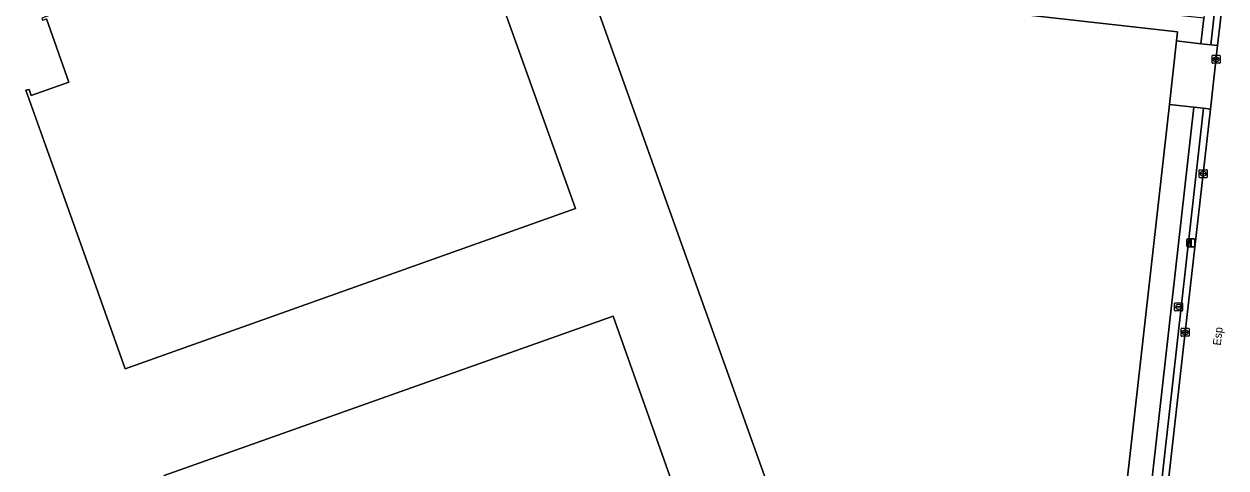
# Model space of a CAD drawing. Extents: x 161385 to 162589, y 388479 to 389756.
# Drawn here: x 162179.9 to 162330.1, y 388598.7 to 388654.2 of the extents above; entities that cross this region are included whole.
import ezdxf

# ---------------------------------------------------------------- set-up
doc = ezdxf.new("R2010")
doc.units = 0
for name, color, linetype in [('IMGEO_Berm_groen', 7, 'Continuous'), ('IMGEO_Brandkraan', 7, 'Continuous'), ('IMGEO_Erf', 7, 'Continuous'), ('IMGEO_Groenvoorziening', 7, 'Continuous'), ('IMGEO_Kolk', 7, 'Continuous'), ('IMGEO_Lichtmast', 7, 'Continuous'), ('IMGEO_Openbare_ruimte_label', 7, 'Continuous'), ('IMGEO_Pand', 7, 'Continuous'), ('IMGEO_Rijbaan_lokaal_gesloten', 7, 'Continuous'), ('IMGEO_Voetpad_open', 7, 'Continuous')]:
    doc.layers.add(name, color=color, linetype=linetype)

msp = doc.modelspace()

# ---------------------------------------------------------------- linework, layer by layer
at = {"layer": 'IMGEO_Berm_groen'}
msp.add_lwpolyline([(162322.88, 388597.19), (162324.97, 388615.65), (162327.23, 388635.47), (162328.13, 388643.54), (162327.27, 388643.64), (162321.79, 388594.96)], dxfattribs=at)
at = {"layer": 'IMGEO_Brandkraan'}
for p, q in [((162323.65, 388618.4), (162323.65, 388619.26)), ((162323.72, 388619.33), (162324.58, 388619.33)), ((162324.58, 388618.33), (162323.72, 388618.33)), ((162323.91, 388618.82), (162323.91, 388618.84)), ((162323.95, 388618.87), (162324.35, 388618.87)), ((162324.35, 388618.79), (162323.95, 388618.79)), ((162324.14, 388619.11), (162324.16, 388619.11)), ((162324.16, 388618.55), (162324.14, 388618.55)), ((162324.39, 388618.84), (162324.39, 388618.82)), ((162324.65, 388619.26), (162324.65, 388618.4))]:
    msp.add_line(p, q, dxfattribs=at)
for points in [[(162323.65, 388618.4), (162323.65, 388619.26)], [(162323.72, 388619.33), (162324.58, 388619.33)], [(162324.58, 388618.33), (162323.72, 388618.33)], [(162324.65, 388619.26), (162324.65, 388618.4)]]:
    msp.add_lwpolyline(points, dxfattribs=at)
for centre, radius, start, end in [((162323.73, 388619.25), 0.0765, 91.552, 178.448), ((162323.73, 388619.25), 0.0765, 91.552, 178.448), ((162323.73, 388618.4), 0.0765, 181.552, 268.448), ((162323.73, 388618.4), 0.0765, 181.552, 268.448), ((162323.95, 388618.83), 0.0403, 85.8775, 175.7526), ((162323.95, 388618.82), 0.0366, 178.938, 274.7102), ((162324.35, 388618.83), 0.0386, 1.7309, 96.639), ((162324.35, 388618.83), 0.043, 264.8664, 352.4533), ((162324.57, 388619.25), 0.0765, 1.552, 88.448), ((162324.57, 388619.25), 0.0765, 1.552, 88.448), ((162324.57, 388618.4), 0.0765, 271.552, 358.448), ((162324.57, 388618.4), 0.0765, 271.552, 358.448)]:
    msp.add_arc(centre, radius, start, end, dxfattribs=at)
for centre, major_axis, ratio, start_param, end_param in [((162324.14, 388618.83), (-0.387, 0.002), 0.722429, 4.712389, 7.853982), ((162324.16, 388618.83), (-0.39, 0.002), 0.717154, 1.570796, 4.712389)]:
    msp.add_ellipse(centre, major_axis=major_axis, ratio=ratio, start_param=start_param, end_param=end_param, dxfattribs=at)
at = {"layer": 'IMGEO_Erf'}
for points in [[(162237.46, 388662.85), (162248.8, 388631.1), (162192.55, 388611.08), (162188.68, 388621.98), (162184.22, 388634.49), (162182.65, 388638.89), (162180.16, 388645.89), (162180.56, 388645.98), (162180.83, 388645.22), (162185.54, 388646.91), (162182.74, 388654.8)], [(162178.21, 388542.32), (162196.49, 388548.83), (162194.91, 388553.16), (162200.28, 388555.21), (162201.15, 388552.67), (162211.61, 388556.41), (162210.55, 388559.77), (162208.46, 388566.35), (162208.62, 388566.4), (162207.46, 388569.58), (162208.17, 388573.43), (162204.37, 388576.76), (162204.53, 388577.63), (162197.44, 388597.74), (162253.52, 388617.68), (162265.26, 388584.52), (162265.03, 388584.45), (162268.12, 388574.72), (162279.12, 388578.18), (162278.24, 388581.06), (162278.06, 388581.59), (162278.17, 388581.63), (162249.79, 388661.1)]]:
    msp.add_lwpolyline(points, dxfattribs=at)
at = {"layer": 'IMGEO_Groenvoorziening'}
msp.add_lwpolyline([(162266.99, 388662.09), (162242.29, 388665.5), (162242.68, 388666.67), (162227.08, 388668.43), (162227.59, 388673.38), (162211.98, 388674.58), (162211.33, 388665.83), (162237.46, 388662.85), (162249.55, 388661.32), (162249.58, 388661.57), (162250.1, 388661.51), (162324.03, 388653.19), (162323.9, 388652.05), (162326.93, 388651.71), (162327.29, 388654.89), (162309.93, 388656.72)], close=True, dxfattribs=at)
for points in [[(162329.34, 388662.16), (162328.16, 388651.57), (162329.02, 388651.48), (162329.38, 388654.67), (162329.47, 388655.51), (162330.07, 388660.3), (162330.03, 388661.07), (162330.02, 388661.17), (162329.72, 388661.78)], [(162326.04, 388643.78), (162323.01, 388644.12), (162317.74, 388597.16)], [(162320.59, 388595.27), (162326.04, 388643.78)]]:
    msp.add_lwpolyline(points, dxfattribs=at)
at = {"layer": 'IMGEO_Kolk'}
for p, q in [((162328.33, 388649.34), (162328.33, 388650.19)), ((162328.4, 388650.26), (162329.26, 388650.26)), ((162328.59, 388649.76), (162328.59, 388649.77)), ((162328.63, 388649.81), (162329.03, 388649.81)), ((162329.03, 388649.72), (162328.63, 388649.72)), ((162328.84, 388649.48), (162328.81, 388649.48)), ((162328.82, 388650.04), (162328.84, 388650.04)), ((162329.07, 388649.77), (162329.07, 388649.76)), ((162329.33, 388650.19), (162329.33, 388649.34)), ((162329.26, 388649.26), (162328.4, 388649.26)), ((162326.8, 388635.97), (162327.65, 388635.97)), ((162326.73, 388635.04), (162326.73, 388635.9)), ((162327.65, 388634.97), (162326.8, 388634.97)), ((162326.98, 388635.46), (162326.98, 388635.48)), ((162327.42, 388635.43), (162327.02, 388635.43)), ((162327.03, 388635.51), (162327.43, 388635.51)), ((162327.21, 388635.75), (162327.24, 388635.75)), ((162327.24, 388635.19), (162327.21, 388635.19)), ((162327.47, 388635.48), (162327.47, 388635.46)), ((162327.73, 388635.9), (162327.73, 388635.04)), ((162324.47, 388615.22), (162324.47, 388616.07)), ((162324.54, 388616.15), (162325.39, 388616.15)), ((162325.39, 388615.15), (162324.54, 388615.15)), ((162324.73, 388615.64), (162324.73, 388615.65)), ((162324.77, 388615.69), (162325.17, 388615.69)), ((162325.16, 388615.6), (162324.77, 388615.6)), ((162324.98, 388615.37), (162324.95, 388615.37)), ((162324.96, 388615.93), (162324.98, 388615.93)), ((162325.21, 388615.65), (162325.21, 388615.64)), ((162325.47, 388616.07), (162325.47, 388615.22))]:
    msp.add_line(p, q, dxfattribs=at)
for points in [[(162328.33, 388649.34), (162328.33, 388650.19)], [(162328.4, 388650.26), (162329.26, 388650.26)], [(162329.33, 388650.19), (162329.33, 388649.34)], [(162329.26, 388649.26), (162328.4, 388649.26)], [(162326.8, 388635.97), (162327.65, 388635.97)], [(162326.73, 388635.04), (162326.73, 388635.9)], [(162327.65, 388634.97), (162326.8, 388634.97)], [(162327.73, 388635.9), (162327.73, 388635.04)], [(162324.47, 388615.22), (162324.47, 388616.07)], [(162324.54, 388616.15), (162325.39, 388616.15)], [(162325.39, 388615.15), (162324.54, 388615.15)], [(162325.47, 388616.07), (162325.47, 388615.22)]]:
    msp.add_lwpolyline(points, dxfattribs=at)
for centre, radius, start, end in [((162328.41, 388650.19), 0.0765, 91.552, 178.448), ((162328.41, 388650.19), 0.0765, 91.552, 178.448), ((162328.63, 388649.77), 0.0403, 85.8775, 175.7526), ((162328.62, 388649.76), 0.0366, 178.938, 274.7102), ((162329.03, 388649.77), 0.0386, 1.7309, 96.639), ((162329.03, 388649.76), 0.043, 264.8664, 352.4533), ((162329.25, 388650.19), 0.0765, 1.552, 88.448), ((162329.25, 388650.19), 0.0765, 1.552, 88.448), ((162328.41, 388649.34), 0.0765, 181.552, 268.448), ((162328.41, 388649.34), 0.0765, 181.552, 268.448), ((162329.25, 388649.34), 0.0765, 271.552, 358.448), ((162329.25, 388649.34), 0.0765, 271.552, 358.448), ((162326.8, 388635.9), 0.0765, 91.552, 178.448), ((162326.8, 388635.9), 0.0765, 91.552, 178.448), ((162327.65, 388635.9), 0.0765, 1.552, 88.448), ((162327.65, 388635.9), 0.0765, 1.552, 88.448), ((162326.8, 388635.05), 0.0765, 181.552, 268.448), ((162326.8, 388635.05), 0.0765, 181.552, 268.448), ((162327.03, 388635.47), 0.0403, 85.8775, 175.7526), ((162327.02, 388635.46), 0.0366, 178.938, 274.7102), ((162327.43, 388635.47), 0.043, 264.8664, 352.4533), ((162327.43, 388635.48), 0.0386, 1.7309, 96.639), ((162327.65, 388635.05), 0.0765, 271.552, 358.448), ((162327.65, 388635.05), 0.0765, 271.552, 358.448), ((162324.54, 388616.07), 0.0765, 91.552, 178.448), ((162324.54, 388616.07), 0.0765, 91.552, 178.448), ((162324.54, 388615.22), 0.0765, 181.552, 268.448), ((162324.54, 388615.22), 0.0765, 181.552, 268.448), ((162324.77, 388615.65), 0.0403, 85.8775, 175.7526), ((162324.76, 388615.64), 0.0366, 178.938, 274.7102), ((162325.17, 388615.65), 0.043, 264.8664, 352.4533), ((162325.17, 388615.65), 0.0386, 1.7309, 96.639), ((162325.39, 388616.07), 0.0765, 1.552, 88.448), ((162325.39, 388616.07), 0.0765, 1.552, 88.448), ((162325.39, 388615.22), 0.0765, 271.552, 358.448), ((162325.39, 388615.22), 0.0765, 271.552, 358.448)]:
    msp.add_arc(centre, radius, start, end, dxfattribs=at)
for centre, major_axis, ratio, start_param, end_param in [((162328.82, 388649.76), (-0.387, 0.002), 0.722429, 4.712389, 7.853982), ((162328.84, 388649.76), (-0.39, 0.002), 0.717154, 1.570796, 4.712389), ((162327.21, 388635.47), (-0.387, 0.002), 0.722429, 4.712389, 7.853982), ((162327.24, 388635.47), (-0.39, 0.002), 0.717154, 1.570796, 4.712389), ((162324.95, 388615.65), (-0.387, 0.002), 0.722429, 4.712389, 7.853982), ((162324.98, 388615.65), (-0.39, 0.002), 0.717154, 1.570796, 4.712389)]:
    msp.add_ellipse(centre, major_axis=major_axis, ratio=ratio, start_param=start_param, end_param=end_param, dxfattribs=at)
at = {"layer": 'IMGEO_Lichtmast'}
for p, q in [((162325.17, 388626.43), (162325.17, 388627.23)), ((162325.17, 388627.23), (162325.17, 388626.43)), ((162325.27, 388627.33), (162326.06, 388627.33)), ((162326.06, 388627.33), (162325.27, 388627.33)), ((162326.16, 388627.23), (162326.16, 388626.43)), ((162326.16, 388626.43), (162326.16, 388627.23)), ((162326.06, 388626.33), (162325.27, 388626.33)), ((162325.27, 388626.33), (162326.06, 388626.33))]:
    msp.add_line(p, q, dxfattribs=at)
msp.add_lwpolyline([(162325.59, 388627.21), (162325.74, 388627.21), (162325.74, 388626.46), (162325.59, 388626.46), (162325.59, 388627.21)], dxfattribs=at)
for centre, start, end in [((162325.27, 388627.23), 90, 180), ((162325.27, 388627.23), 90, 180), ((162326.06, 388627.23), 0, 90), ((162326.06, 388627.23), 360, 90), ((162325.27, 388626.43), 180, 270), ((162325.27, 388626.43), 180, 270), ((162326.06, 388626.43), 270, 0), ((162326.06, 388626.43), 270, 0)]:
    msp.add_arc(centre, 0.1, start, end, dxfattribs=at)
at = {"layer": 'IMGEO_Pand'}
for points in [[(162211.33, 388665.83), (162201.17, 388666.99), (162202.8, 388662.3), (162182.16, 388654.92), (162182.25, 388654.64), (162182.74, 388654.8), (162185.54, 388646.91), (162180.83, 388645.22), (162180.56, 388645.98), (162180.16, 388645.89), (162182.65, 388638.89), (162184.22, 388634.49), (162188.68, 388621.98), (162192.55, 388611.08), (162248.8, 388631.1), (162237.46, 388662.85)], [(162260.96, 388575.65), (162261.06, 388575.68), (162258.9, 388582.53), (162265.03, 388584.45), (162265.26, 388584.52), (162253.52, 388617.68), (162197.44, 388597.74), (162204.53, 388577.63), (162204.37, 388576.76), (162208.17, 388573.43), (162207.46, 388569.58), (162208.62, 388566.4), (162208.46, 388566.35), (162210.55, 388559.77), (162235.58, 388567.65), (162235.13, 388569.05), (162242.07, 388571.24), (162242.52, 388569.84), (162242.86, 388569.95)]]:
    msp.add_lwpolyline(points, close=True, dxfattribs=at)
for points in [[(162323.01, 388644.12), (162323.9, 388652.05), (162324.03, 388653.19), (162250.1, 388661.51), (162249.58, 388661.57), (162249.55, 388661.32), (162249.54, 388661.18), (162249.77, 388661.15), (162249.79, 388661.1), (162278.17, 388581.63), (162278.06, 388581.59), (162278.24, 388581.06), (162300.93, 388588.25), (162300.41, 388589.92), (162304.82, 388591.32), (162306.53, 388591.87), (162307.06, 388590.2), (162313.95, 388592.38)], [(162317.74, 388597.16), (162323.01, 388644.12)]]:
    msp.add_lwpolyline(points, dxfattribs=at)
at = {"layer": 'IMGEO_Rijbaan_lokaal_gesloten'}
msp.add_lwpolyline([(162330.02, 388661.17), (162330.03, 388661.07), (162330.07, 388660.3), (162329.47, 388655.51), (162329.38, 388654.67), (162329.02, 388651.48), (162328.13, 388643.54), (162327.23, 388635.47), (162324.97, 388615.65), (162322.88, 388597.19)], dxfattribs=at)
at = {"layer": 'IMGEO_Voetpad_open'}
for points in [[(162328.43, 388662.64), (162328.16, 388662.67), (162328.02, 388661.4), (162327.29, 388654.89), (162326.93, 388651.71), (162328.16, 388651.57), (162329.34, 388662.16)], [(162321.79, 388594.96), (162327.27, 388643.64), (162326.04, 388643.78), (162320.59, 388595.27)]]:
    msp.add_lwpolyline(points, dxfattribs=at)
msp.add_lwpolyline([(162329.02, 388651.48), (162328.16, 388651.57), (162326.93, 388651.71), (162323.9, 388652.05), (162323.01, 388644.12), (162326.04, 388643.78), (162327.27, 388643.64), (162328.13, 388643.54)], close=True, dxfattribs=at)

# ---------------------------------------------------------------- texts
at = {"layer": 'IMGEO_Openbare_ruimte_label'}
msp.add_text('Esp', height=1, rotation=83.5713, dxfattribs=at).set_placement((162329.41, 388613.96))

doc.saveas('drawing.dxf')
